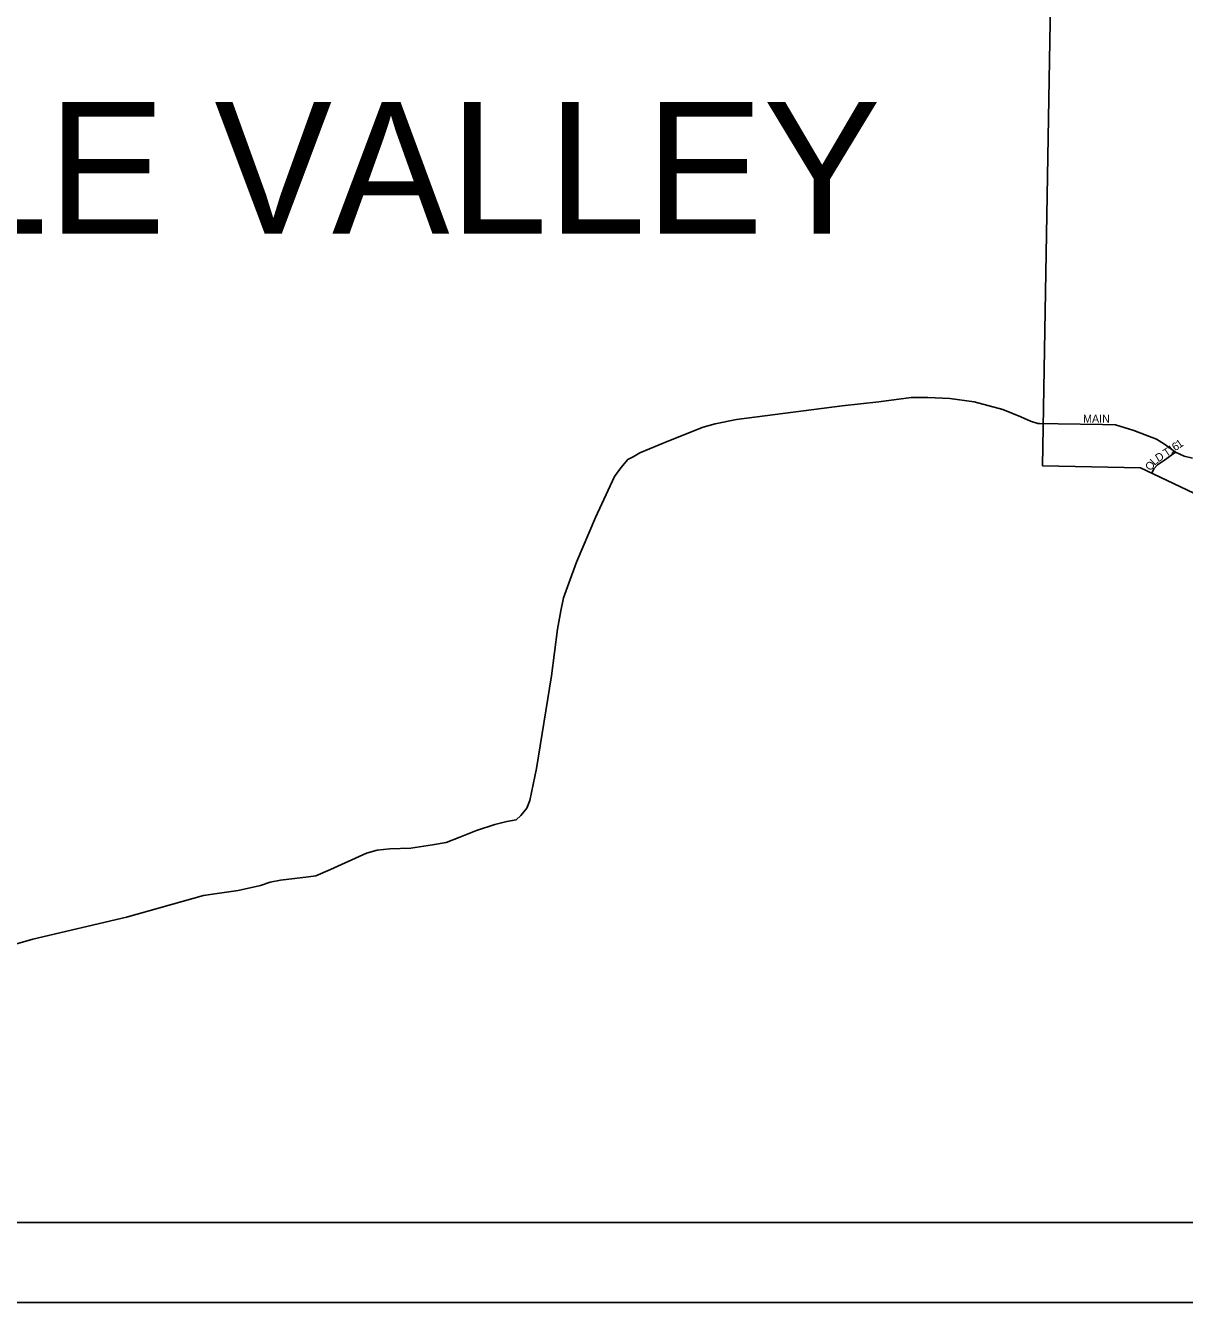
# Model space of a CAD drawing. Extents: x 0 to 34, y 0 to 22.
# Drawn here: x 24.277 to 25.646, y 9.524 to 11.032 of the extents above; entities that cross this region are included whole.
import ezdxf

# ---------------------------------------------------------------- set-up
doc = ezdxf.new("R2010")
doc.units = 0
for name, color, linetype in [('Default', 7, 'Continuous'), ('GM_X_City_Street', 7, 'Continuous'), ('GM_X_City_Street_Text', 7, 'Continuous'), ('GM_X_Corporation', 7, 'Continuous'), ('GM_X_Unincorporated_Text', 7, 'Continuous')]:
    doc.layers.add(name, color=color, linetype=linetype)

msp = doc.modelspace()

# ---------------------------------------------------------------- linework, layer by layer
at = {"layer": 'Default'}
msp.add_line((30.697, 9.6182), (19.8526, 9.6182), dxfattribs=at)
msp.add_lwpolyline([(19.7581, 20.557), (30.7915, 20.557), (30.7915, 9.5237), (19.7581, 9.5237)], close=True, dxfattribs=at)
msp.add_lwpolyline([(24.2598, 9.9454), (24.2855, 9.9527), (24.3962, 9.9789), (24.4873, 10.0041), (24.5035, 10.0067), (24.5281, 10.0102), (24.5545, 10.0163), (24.5659, 10.0201), (24.5783, 10.0224), (24.6112, 10.0262), (24.6199, 10.0277), (24.6373, 10.0349), (24.6796, 10.0543), (24.6924, 10.0577), (24.7071, 10.0593), (24.7321, 10.0601), (24.7578, 10.0643), (24.7736, 10.0669), (24.7899, 10.073), (24.8095, 10.081), (24.8314, 10.0882), (24.8454, 10.0916), (24.8564, 10.0936), (24.862, 10.0989), (24.8692, 10.1076), (24.8726, 10.1163), (24.8805, 10.1541), (24.8982, 10.2639), (24.9053, 10.3188), (24.9091, 10.3404), (24.9125, 10.3559), (24.9185, 10.3733), (24.9276, 10.398), (24.9502, 10.4506), (24.9724, 10.4991), (24.98, 10.5093), (24.9883, 10.5192), (24.9947, 10.5222), (25.0026, 10.5271), (25.0366, 10.5412), (25.0774, 10.5575), (25.0914, 10.5613), (25.1167, 10.5663), (25.2414, 10.5828), (25.2849, 10.5874), (25.323, 10.5923), (25.3427, 10.5924), (25.3684, 10.5913), (25.3971, 10.5872), (25.4311, 10.5781), (25.4523, 10.5695), (25.464, 10.5646), (25.4723, 10.5619), (25.4743, 10.5619), (25.4746, 10.5618)], dxfattribs=at)
at = {"layer": 'GM_X_City_Street'}
for points in [[(25.4746, 10.5618), (25.4965, 10.5612), (25.549, 10.5605), (25.5642, 10.5602), (25.5857, 10.5534), (25.6125, 10.5432), (25.622, 10.5375), (25.6352, 10.5277), (25.6451, 10.5232), (25.6553, 10.5209)], [(25.6069, 10.5031), (25.6095, 10.5082), (25.6136, 10.5131), (25.6222, 10.5186), (25.6352, 10.5277)]]:
    msp.add_lwpolyline(points, dxfattribs=at)
at = {"layer": 'GM_X_Corporation'}
msp.add_lwpolyline([(25.9839, 11.2013), (25.9758, 10.8493), (26.0003, 10.8138), (26.0373, 10.7186), (26.1483, 10.7197), (26.1605, 10.702), (26.2388, 10.7027), (26.2375, 10.7269), (26.2453, 10.8102), (26.2937, 10.8129), (26.2856, 10.771), (26.2797, 10.7327), (26.2728, 10.7107), (26.268, 10.7008), (26.2431, 10.6885), (26.276, 10.5386), (26.0463, 10.4945), (25.9914, 10.6078), (25.7766, 10.4938), (25.6566, 10.4793), (25.5936, 10.5094), (25.478, 10.5119), (25.4897, 11.1961)], close=True, dxfattribs=at)

# ---------------------------------------------------------------- texts
at = {"layer": 'GM_X_City_Street_Text'}
for s, rotation, p in [('MAIN', 0, (25.5259, 10.5626)), ('1', 34.1366, (25.6395, 10.5321)), ('D', 31.2524, (25.6147, 10.5159)), ('T', 33.6249, (25.6243, 10.5218)), ('1', 34.1427, (25.6299, 10.5256)), ('6', 34.1145, (25.6347, 10.5288)), ('O', 55.2551, (25.606, 10.5052)), ('L', 44.1305, (25.6104, 10.5116))]:
    msp.add_text(s, height=0.00945, rotation=rotation, dxfattribs=at).set_placement(p)
at = {"layer": 'GM_X_Unincorporated_Text'}
msp.add_text('BELLE VALLEY', height=0.155676, rotation=0, dxfattribs=at).set_placement((23.7942, 10.7858))

doc.saveas('drawing.dxf')
